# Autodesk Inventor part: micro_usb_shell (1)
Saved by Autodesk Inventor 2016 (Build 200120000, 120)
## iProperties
Created: 2016-09
Part Number: micro_usb_shell (1)
Material: Generic
Document SubType Name: Modeling
Designer: Administrator
Appearance: Generic
Author: Administrator
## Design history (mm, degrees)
feature "Body1"
body "Solid1"
